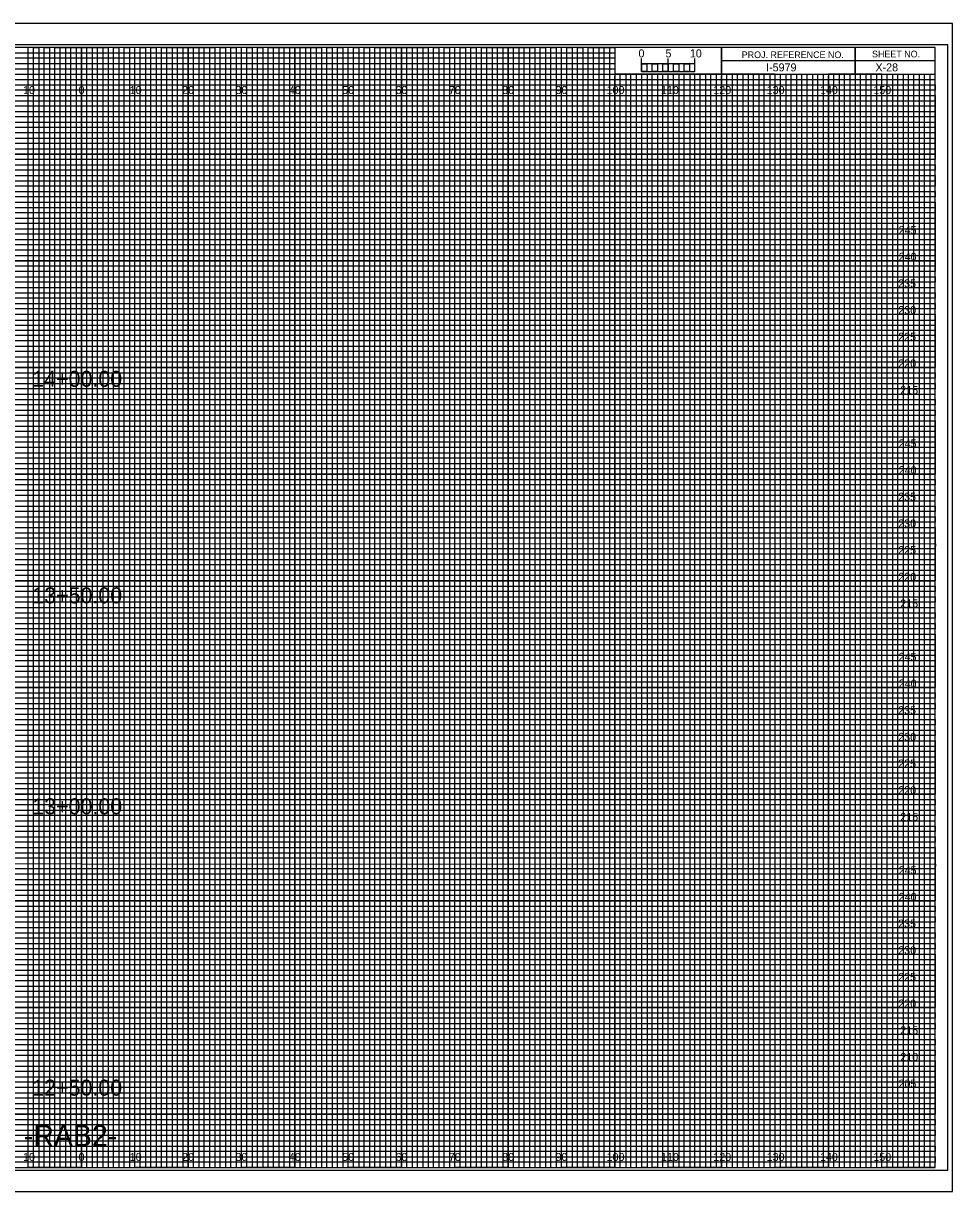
# Model space of a CAD drawing. Extents: x -13 to 323, y -5 to 654.
# Drawn here: x 149.1 to 323.3, y 215.5 to 434.5 of the extents above; entities that cross this region are included whole.
import ezdxf

# ---------------------------------------------------------------- set-up
doc = ezdxf.new("R2010")
doc.units = 0
for name, color, linetype in [('Exist CMT Pavement', 7, 'Continuous'), ('Exist Cross Section Cell', 7, 'Continuous'), ('Exist XS Center Line Elevation Label', 7, 'Continuous'), ('Exist XS Ground Line', 7, 'Continuous'), ('Prop CMT Conc Surface', 7, 'Continuous'), ('Prop CMT Concrete Structures', 7, 'Continuous'), ('Prop CMT DNC', 7, 'Continuous'), ('Prop CMT Pvmt Course 1 CG', 7, 'Continuous'), ('Prop CMT Pvmt Course 1 Wedge', 7, 'Continuous'), ('Prop CMT Pvmt Course 2', 7, 'Continuous'), ('Prop CMT Pvmt Course 2 Wedge', 7, 'Continuous'), ('Prop CMT Pvmt Course 3', 7, 'Continuous'), ('Prop CMT Pvmt Course 3 Wedge', 7, 'Continuous'), ('Prop CMT Pvmt Surface', 7, 'Continuous'), ('Prop CMT Shear Line', 7, 'Continuous'), ('Prop CMT Slope Grass', 7, 'Continuous'), ('Prop CMT Subgrade Earthwork', 7, 'Continuous')]:
    doc.layers.add(name, color=color, linetype=linetype)

msp = doc.modelspace()

# ---------------------------------------------------------------- linework, layer by layer
at = {"layer": 'Exist XS Center Line Elevation Label'}
for points in [[(145, 220), (155, 220), (155, 430), (165, 430), (165, 220), (175, 220), (175, 430), (185, 430), (185, 220), (195, 220), (195, 430), (205, 430), (205, 220), (215, 220), (215, 430), (225, 430), (225, 220), (235, 220), (235, 430), (245, 430), (245, 220), (255, 220), (255, 430), (259.93, 430), (260, 430), (260, 425), (264.99, 425), (264.99, 220), (275, 220), (275, 425), (285, 425), (285, 220), (295, 220), (295, 425), (305, 425), (305, 220), (315, 220), (315, 425)], [(0, 425), (275, 425)], [(0, 405), (320, 405), (320, 415), (0, 415)], [(0, 385), (320, 385), (320, 395), (0, 395)], [(0, 365), (320, 365), (320, 375), (0, 375)], [(0, 345), (320, 345), (320, 355), (0, 355)], [(0, 325), (320, 325), (320, 335), (0, 335)], [(0, 305), (320, 305), (320, 315), (0, 315)], [(0, 285), (320, 285), (320, 295), (0, 295)], [(0, 265), (320, 265), (320, 275), (0, 275)], [(0, 245), (320, 245), (320, 255), (0, 255)], [(0, 225), (320, 225), (320, 235), (0, 235)]]:
    msp.add_lwpolyline(points, dxfattribs=at)
at = {"layer": 'Exist XS Ground Line'}
for p, q in [((150, 430), (140, 430)), ((150, 220), (150, 430)), ((170, 430), (160, 430)), ((160, 430), (160, 220)), ((170, 220), (170, 430)), ((190, 430), (180, 430)), ((180, 430), (180, 220)), ((190, 220), (190, 430)), ((210, 430), (200, 430)), ((200, 430), (200, 220)), ((210, 220), (210, 430)), ((230, 430), (220, 430)), ((220, 430), (220, 220)), ((230, 220), (230, 430)), ((250, 430), (240, 430)), ((240, 430), (240, 220)), ((250, 220), (250, 430)), ((260, 430), (260, 220)), ((270, 220), (270, 425)), ((290, 425), (280, 425)), ((280, 425), (280, 220)), ((290, 220), (290, 425)), ((310, 425), (300, 425)), ((300, 425), (300, 220)), ((310, 220), (310, 425)), ((160, 220), (150, 220)), ((180, 220), (170, 220)), ((200, 220), (190, 220)), ((220, 220), (210, 220)), ((240, 220), (230, 220)), ((260, 220), (250, 220)), ((280, 220), (270, 220)), ((300, 220), (290, 220)), ((320, 220), (310, 220)), ((320, 220), (320, 220))]:
    msp.add_line(p, q, dxfattribs=at)
for points in [[(0, 420), (320, 420), (320, 410), (0, 410)], [(0, 400), (320, 400), (320, 390), (0, 390)], [(0, 380), (320, 380), (320, 370), (0, 370)], [(0, 360), (320, 360), (320, 350), (0, 350)], [(0, 340), (320, 340), (320, 330), (0, 330)], [(0, 320), (320, 320), (320, 310), (0, 310)], [(0, 300), (320, 300), (320, 290), (0, 290)], [(0, 280), (320, 280), (320, 270), (0, 270)], [(0, 260), (320, 260), (320, 250), (0, 250)], [(0, 240), (320, 240), (320, 230), (0, 230)]]:
    msp.add_lwpolyline(points, dxfattribs=at)
at = {"layer": 'Prop CMT Conc Surface'}
msp.add_lwpolyline([(-13.4, 215.5), (323.3, 215.5), (323.3, 434.5), (-13.4, 434.5)], close=True, dxfattribs=at)
at = {"layer": 'Prop CMT Concrete Structures'}
for p, q in [((305, 430), (305, 425)), ((305, 425), (305, 430)), ((280, 427.5), (280, 425)), ((320, 427.49), (280, 427.49)), ((280, 425), (320, 425))]:
    msp.add_line(p, q, dxfattribs=at)
for points in [[(320, 430), (0, 430), (0, 220), (320, 220)], [(280, 430), (260, 430), (260, 425.03), (280, 425.03)], [(320, 430), (280, 430), (280, 425), (320, 425)]]:
    msp.add_lwpolyline(points, close=True, dxfattribs=at)
at = {"layer": 'Prop CMT DNC'}
for p, q in [((267, 425), (266.01, 425)), ((266.01, 425), (266.01, 220)), ((267, 220), (267, 425)), ((269, 425), (268, 425)), ((268, 425), (268, 220)), ((269, 220), (269, 425)), ((266.01, 220), (265, 220)), ((268, 220), (267, 220))]:
    msp.add_line(p, q, dxfattribs=at)
for points in [[(150, 220), (151, 220), (151, 430), (152, 430), (152, 220)], [(152, 220), (153, 220), (153, 430), (154, 430), (154, 220)], [(155, 220), (156, 220), (156, 430), (157, 430), (157, 220)], [(157, 220), (158, 220), (158, 430), (159, 430), (159, 220)], [(160, 220), (161, 220), (161, 430), (162, 430), (162, 220)], [(162, 220), (163, 220), (163, 430), (164, 430), (164, 220)], [(165, 220), (166, 220), (166, 430), (167, 430), (167, 220)], [(167, 220), (168, 220), (168, 430), (169, 430), (169, 220)], [(170, 220), (171, 220), (171, 430), (172, 430), (172, 220)], [(172, 220), (173, 220), (173, 430), (174, 430), (174, 220)], [(175, 220), (176, 220), (176, 430), (177, 430), (177, 220)], [(177, 220), (178, 220), (178, 430), (179, 430), (179, 220)], [(180, 220), (181, 220), (181, 430), (182, 430), (182, 220)], [(182, 220), (183, 220), (183, 430), (184, 430), (184, 220)], [(185, 220), (186, 220), (186, 430), (187, 430), (187, 220)], [(187, 220), (188, 220), (188, 430), (189, 430), (189, 220)], [(190, 220), (191, 220), (191, 430), (192, 430), (192, 220)], [(192, 220), (193, 220), (193, 430), (194, 430), (194, 220)], [(195, 220), (196, 220), (196, 430), (197, 430), (197, 220)], [(197, 220), (198, 220), (198, 430), (199, 430), (199, 220)], [(200, 220), (201, 220), (201, 430), (202, 430), (202, 220)], [(202, 220), (203, 220), (203, 430), (204, 430), (204, 220)], [(205, 220), (206, 220), (206, 430), (207, 430), (207, 220)], [(207, 220), (208, 220), (208, 430), (209, 430), (209, 220)], [(210, 220), (211, 220), (211, 430), (212, 430), (212, 220)], [(212, 220), (213, 220), (213, 430), (214, 430), (214, 220)], [(215, 220), (216, 220), (216, 430), (217, 430), (217, 220)], [(217, 220), (218, 220), (218, 430), (219, 430), (219, 220)], [(220, 220), (221, 220), (221, 430), (222, 430), (222, 220)], [(222, 220), (223, 220), (223, 430), (224, 430), (224, 220)], [(225, 220), (226, 220), (226, 430), (227, 430), (227, 220)], [(227, 220), (228, 220), (228, 430), (229, 430), (229, 220)], [(230, 220), (231, 220), (231, 430), (232, 430), (232, 220)], [(232, 220), (233, 220), (233, 430), (234, 430), (234, 220)], [(235, 220), (236, 220), (236, 430), (237, 430), (237, 220)], [(237, 220), (238, 220), (238, 430), (239, 430), (239, 220)], [(240, 220), (241, 220), (241, 430), (242, 430), (242, 220)], [(242, 220), (243, 220), (243, 430), (244, 430), (244, 220)], [(245, 220), (246, 220), (246, 430), (247, 430), (247, 220)], [(247, 220), (248, 220), (248, 430), (249, 430), (249, 220)], [(250, 220), (251, 220), (251, 430), (252, 430), (252, 220)], [(252, 220), (253, 220), (253, 430), (254, 430), (254, 220)], [(255, 220), (256, 220), (256, 430), (257, 430), (257, 220)], [(257, 220), (258, 220), (258, 430), (259, 430), (259, 220)], [(260, 220), (261, 220), (261, 425), (262.02, 425), (262.02, 220)], [(262, 220), (263, 220), (263, 425), (263.99, 425), (263.99, 220)], [(270, 220), (270.98, 220), (270.98, 425), (272, 425), (272, 220)], [(272, 220), (273, 220), (273, 425), (274.05, 425), (274.05, 220)], [(275, 220), (276, 220), (276, 425), (277, 425), (277, 220)], [(277, 220), (278, 220), (278, 425), (279, 425), (279, 220)], [(280, 220), (281, 220), (281, 425), (282, 425), (282, 220)], [(282, 220), (283, 220), (283, 425), (284, 425), (284, 220)], [(285, 220), (286, 220), (286, 425), (287, 425), (287, 220)], [(287, 220), (288, 220), (288, 425), (289, 425), (289, 220)], [(290, 220), (291, 220), (291, 425), (292, 425), (292, 220)], [(292, 220), (293, 220), (293, 425), (294, 425), (294, 220)], [(295, 220), (296, 220), (296, 425), (297, 425), (297, 220)], [(297, 220), (298, 220), (298, 425), (299, 425), (299, 220)], [(300, 220), (301, 220), (301, 425), (302, 425), (302, 220)], [(302, 220), (303, 220), (303, 425), (304, 425), (304, 220)], [(305, 220), (306, 220), (306, 425), (307, 425), (307, 220)], [(307, 220), (308, 220), (308, 425), (309, 425), (309, 220)], [(310, 220), (311, 220), (311, 425), (312, 425), (312, 220)], [(312, 220), (313, 220), (313, 425), (314, 425), (314, 220)], [(315, 220), (316, 220), (316, 425), (317, 425), (317, 220)], [(317, 220), (318, 220), (318, 425), (319, 425), (319, 220)]]:
    msp.add_lwpolyline(points, dxfattribs=at)
at = {"layer": 'Prop CMT Pvmt Course 1 Wedge'}
for p, q in [((323.3, 434.5), (-13.4, 434.5)), ((-13.4, 215.5), (323.3, 215.5))]:
    msp.add_line(p, q, dxfattribs=at)
at = {"layer": 'Prop CMT Pvmt Course 2'}
msp.add_lwpolyline([(-10.8, 219.5), (322.4, 219.5), (322.4, 430.5), (-10.8, 430.5)], close=True, dxfattribs=at)
at = {"layer": 'Prop CMT Pvmt Course 3'}
for p, q in [((150, 220), (150, 430)), ((160, 220), (160, 430)), ((170, 220), (170, 430)), ((180, 220), (180, 430)), ((190, 220), (190, 430)), ((200, 220), (200, 430)), ((210, 220), (210, 430)), ((220, 220), (220, 430)), ((230, 220), (230, 430)), ((240, 220), (240, 430)), ((250, 220), (250, 430)), ((260, 220), (260, 424.69)), ((270, 220), (270, 424.69)), ((280, 220), (280, 424.69)), ((290, 220), (290, 424.69)), ((300, 220), (300, 424.69)), ((310, 220), (310, 424.69)), ((0, 420), (320, 420)), ((0, 410), (320, 410)), ((0, 400), (320, 400)), ((0, 390), (320, 390)), ((0, 380), (320, 380)), ((0, 370), (320, 370)), ((0, 360), (320, 360)), ((0, 350), (320, 350)), ((0, 340), (320, 340)), ((0, 330), (320, 330)), ((0, 320), (320, 320)), ((0, 310), (320, 310)), ((0, 300), (320, 300)), ((0, 290), (320, 290)), ((0, 280), (320, 280)), ((0, 270), (320, 270)), ((0, 260), (320, 260)), ((0, 250), (320, 250)), ((0, 240), (320, 240)), ((0, 230), (320, 230))]:
    msp.add_line(p, q, dxfattribs=at)
at = {"layer": 'Prop CMT Slope Grass'}
for p, q in [((265, 425.49), (265, 427.9)), ((265, 426.9), (265, 427.9)), ((270, 425.49), (270, 427.9)), ((275, 425.49), (275, 427.9)), ((275, 426.9), (275, 427.9))]:
    msp.add_line(p, q, dxfattribs=at)
for points in [[(275, 426.9), (265, 426.9), (265, 425.49), (275, 425.49)], [(265, 426.9), (266, 426.9), (266, 425.49), (265, 425.49)], [(267, 426.9), (268, 426.9), (268, 425.49), (267, 425.49)], [(269, 426.9), (270, 426.9), (270, 425.49), (269, 425.49)], [(271, 426.9), (272, 426.9), (272, 425.49), (271, 425.49)], [(273, 426.9), (274, 426.9), (274, 425.49), (273, 425.49)]]:
    msp.add_lwpolyline(points, close=True, dxfattribs=at)
at = {"layer": 'Prop CMT Subgrade Earthwork'}
for p, q in [((0, 429), (260, 429)), ((260, 427.98), (0, 427.98)), ((260, 429), (260, 427.98)), ((0, 427), (260, 427)), ((260, 425.89), (0, 425.89)), ((260, 427), (260, 425.89)), ((0, 424), (320, 424))]:
    msp.add_line(p, q, dxfattribs=at)
for points in [[(0, 423), (270, 423), (320, 423), (320, 422), (0, 422)], [(0, 421), (320, 421), (320, 419), (0, 419)], [(0, 418), (320, 418), (320, 417), (0, 416.98)], [(0, 416), (320, 416), (320, 414), (0, 414)], [(0, 413), (320, 413), (320, 412), (0, 412)], [(0, 411), (320, 411), (320, 409), (0, 409)], [(0, 408), (320, 408), (320, 407), (0, 407)], [(0, 406), (320, 406), (320, 404), (0, 404)], [(0, 403), (320, 403), (320, 402), (0, 402)], [(0, 401), (320, 401), (320, 399), (0, 399)], [(0, 398), (320, 398), (320, 397), (0, 397)], [(0, 396), (320, 396), (320, 393.95), (320, 393), (320, 392), (0, 392)], [(0, 394), (320, 394), (320, 393), (0, 393)], [(0, 391), (320, 391), (320, 389), (0, 389.03)], [(0, 389.03), (320, 389), (320, 388), (0, 388)], [(0, 387), (320, 387), (320, 386), (0, 386)], [(0, 384), (320, 384), (320, 383), (0, 383)], [(0, 382), (320, 382), (320, 381), (0, 381)], [(-0.07, 378.89), (320, 378.89), (320, 377.88), (-0.07, 377.88)], [(0, 377), (320, 377), (320, 376), (0, 376)], [(0, 374), (320, 374), (320, 373), (0, 373)], [(0, 372), (320, 372), (320, 371), (0, 371)], [(0, 369), (320, 369), (320, 368), (0, 368)], [(0, 367), (320, 367), (320, 366), (0, 366)], [(0, 364), (320, 364), (320, 363), (0, 363)], [(0, 362), (320, 362), (320, 361), (0, 361)], [(0, 359), (320, 359), (319.99, 357.98), (0, 358)], [(0, 357), (320, 357), (320, 356), (0, 356)], [(0, 354), (320, 354), (320, 353), (0, 353)], [(0, 352), (320, 352), (320, 351), (0, 351)], [(0, 349), (320, 349), (320, 348), (0, 348)], [(0, 347), (320, 347), (320, 346), (0, 346)], [(0, 344), (320, 344), (320, 343), (0, 343)], [(0, 342), (320, 342), (320, 341), (0, 341)], [(0, 339), (320, 339), (320, 338), (0, 338)], [(0, 336.99), (320.07, 336.91), (320, 336), (0, 336)], [(0, 334), (320, 334), (320, 333), (0, 333)], [(0, 332), (320, 332), (320, 331), (0, 331)], [(0, 329), (320, 329), (320, 328), (0, 328)], [(0, 327), (320, 327), (320, 326), (0, 326)], [(0, 324), (320, 324), (320, 323), (0, 323)], [(0, 322), (320, 322), (320, 321), (0, 321)], [(0, 319), (320, 319), (320, 318), (0, 318)], [(0, 317), (320, 317), (320, 316), (0, 316)], [(0, 314), (320, 314), (320, 313), (0, 313)], [(0, 312), (320, 312), (320, 311), (0, 311)], [(0, 309), (320, 309), (320, 308), (0, 308)], [(0, 307), (320, 307), (320, 306), (0, 306)], [(0, 304), (320, 304), (320, 303), (0, 303)], [(0, 302), (320, 302), (320, 301), (0, 301)], [(0, 299), (320, 299), (319.99, 297.98), (0, 298)], [(0, 297), (320, 297), (320, 296), (0, 296)], [(0, 294), (320, 294), (320, 293), (0, 293)], [(0, 292), (320, 292), (320, 291), (0, 291)], [(0, 289), (320, 289), (320, 288), (0, 288)], [(0, 287), (320, 287), (320, 286), (0, 286)], [(0, 284), (320, 284), (320, 283), (0, 283)], [(0, 282), (320, 282), (320, 281), (0, 281)], [(0, 279), (320, 279), (320, 278), (0, 278)], [(0, 276.99), (320.07, 276.91), (320, 276), (0, 276)], [(0, 274), (320, 274), (320, 273), (0, 273)], [(0, 272), (320, 272), (320, 271), (0, 271)], [(0, 269), (320, 269), (320, 268), (0, 268)], [(0, 267), (320, 267), (320, 266), (0, 266)], [(0, 264), (320, 264), (320, 263), (0, 263)], [(0, 262), (320, 262), (320, 261), (0, 261)], [(0, 259), (320, 259), (320, 258), (0, 258)], [(0, 257), (320, 257), (320, 256), (0, 256)], [(0, 254), (320, 254), (320, 253), (0, 253)], [(0, 252), (320, 252), (320, 251), (0, 251)], [(0, 249), (320, 249), (320, 248), (0, 248)], [(0, 247), (320, 247), (320, 246), (0, 246)], [(0, 244), (320, 244), (320, 243), (0, 243)], [(0, 242), (320, 242), (320, 241), (0, 241)], [(0, 239), (320, 239), (320, 238), (0, 238)], [(0, 237), (320, 237), (320, 236), (0, 236)], [(0, 234), (320, 234), (320, 233), (0, 233)], [(0, 232), (320, 232), (320, 231), (0, 231)], [(0, 229), (320, 229), (320, 228), (0, 228)], [(0, 227), (320, 227), (320, 226), (0, 226)], [(0, 224), (320, 224), (320, 223), (0, 223)], [(0, 222), (320, 222), (320, 221), (0, 221)]]:
    msp.add_lwpolyline(points, dxfattribs=at)

# ---------------------------------------------------------------- texts
at = {"layer": 'Exist CMT Pavement'}
msp.add_text('I-5979', height=1.5, dxfattribs=at).set_placement((288.34, 425.5))
at = {"layer": 'Exist Cross Section Cell'}
for s, p in [('10', (149.04, 421.25)), ('0', (159.45, 421.25)), ('0', (159.45, 421.25)), ('10', (169.04, 421.25)), ('20', (178.86, 421.25)), ('30', (188.86, 421.25)), ('40', (198.86, 421.25)), ('50', (208.86, 421.25)), ('60', (218.86, 421.25)), ('70', (228.86, 421.25)), ('80', (238.86, 421.25)), ('90', (248.86, 421.25)), ('100', (258.44, 421.25)), ('110', (268.62, 421.25)), ('120', (278.44, 421.25)), ('130', (288.44, 421.25)), ('140', (298.44, 421.25)), ('150', (308.44, 421.25)), ('10', (149.04, 221.25)), ('0', (159.45, 221.25)), ('0', (159.45, 221.25)), ('10', (169.04, 221.25)), ('20', (178.86, 221.25)), ('30', (188.86, 221.25)), ('40', (198.86, 221.25)), ('50', (208.86, 221.25)), ('60', (218.86, 221.25)), ('70', (228.86, 221.25)), ('80', (238.86, 221.25)), ('90', (248.86, 221.25)), ('100', (258.44, 221.25)), ('110', (268.62, 221.25)), ('120', (278.44, 221.25)), ('130', (288.44, 221.25)), ('140', (298.44, 221.25)), ('150', (308.44, 221.25))]:
    msp.add_text(s, height=1.5, dxfattribs=at).set_placement(p)
at = {"layer": 'Prop CMT Concrete Structures'}
for s, p in [('PROJ. REFERENCE NO.', (283.77, 427.99)), ('SHEET NO.', (308.19, 428.12))]:
    msp.add_text(s, height=1.25, dxfattribs=at).set_placement(p)
at = {"layer": 'Prop CMT Pvmt Course 1 CG'}
for s, p in [('5', (269.47, 428.12)), ('10', (274.04, 428.12))]:
    msp.add_text(s, height=1.5, dxfattribs=at).set_placement(p)
at = {"layer": 'Prop CMT Pvmt Course 2 Wedge'}
for s, p in [('245', (313.18, 395)), ('240', (313.19, 390)), ('235', (313.09, 385)), ('230', (313.11, 380)), ('225', (313.1, 375)), ('220', (313.12, 370)), ('215', (313.48, 365)), ('245', (313.18, 355)), ('240', (313.19, 350)), ('235', (313.09, 345)), ('230', (313.11, 340)), ('225', (313.1, 335)), ('220', (313.12, 330)), ('215', (313.48, 325)), ('245', (313.18, 315)), ('240', (313.19, 310)), ('235', (313.09, 305)), ('230', (313.11, 300)), ('225', (313.1, 295)), ('220', (313.12, 290)), ('215', (313.48, 285)), ('245', (313.18, 275)), ('240', (313.19, 270)), ('235', (313.09, 265)), ('230', (313.11, 260)), ('225', (313.1, 255)), ('220', (313.12, 250)), ('215', (313.48, 245)), ('210', (313.5, 240)), ('205', (313.15, 235))]:
    msp.add_text(s, height=1.5, dxfattribs=at).set_placement(p)
at = {"layer": 'Prop CMT Pvmt Course 3 Wedge'}
for s, p in [('14+00.00', (150.77, 366.37)), ('13+50.00', (150.77, 325.78)), ('13+00.00', (150.77, 286.23)), ('12+50.00', (150.77, 233.49))]:
    msp.add_text(s, height=3, dxfattribs=at).set_placement(p)
at = {"layer": 'Prop CMT Pvmt Surface'}
msp.add_text('-RAB2-', height=4, dxfattribs=at).set_placement((149.17, 224))
at = {"layer": 'Prop CMT Shear Line'}
msp.add_text('X-28', height=1.5, dxfattribs=at).set_placement((308.83, 425.5))
at = {"layer": 'Prop CMT Slope Grass'}
msp.add_text('0', height=1.5, dxfattribs=at).set_placement((264.41, 428.12))

doc.saveas('drawing.dxf')
